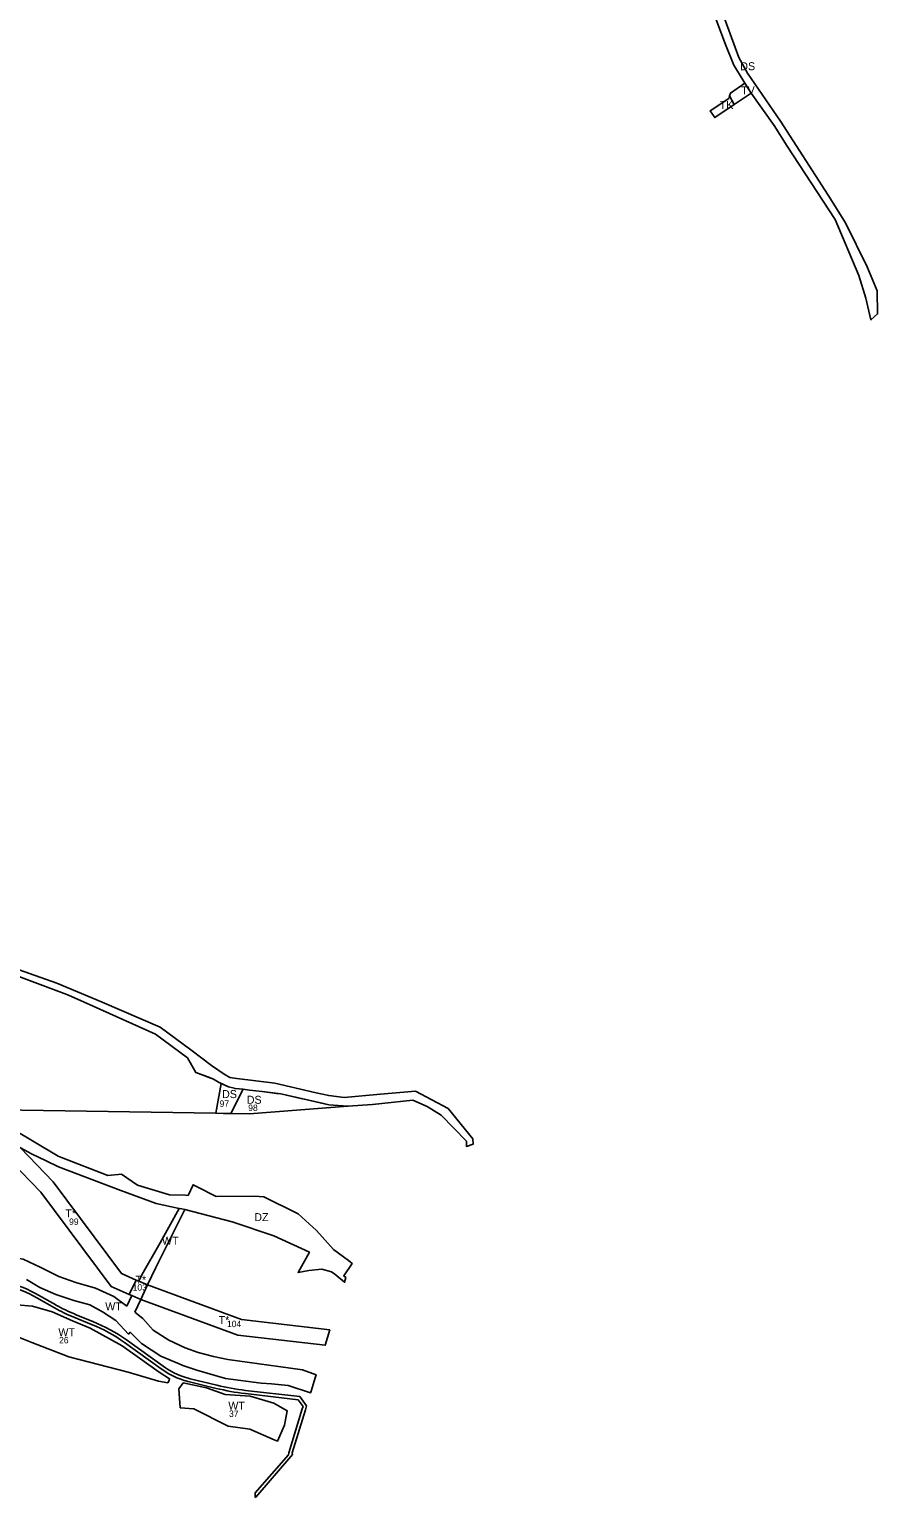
# Model space of a CAD drawing. Extents: x -521621 to -516769, y -1190068 to -1185078.
# Drawn here: x -517829 to -516769, y -1188185 to -1186349 of the extents above; entities that cross this region are included whole.
import ezdxf

# ---------------------------------------------------------------- set-up
doc = ezdxf.new("R2010")
doc.units = 0
for name, color, linetype in [('fpl_id', 7, 'Continuous'), ('v_infrastr_n', 7, 'Continuous'), ('v_infrastr_s', 7, 'Continuous'), ('voda_n', 7, 'Continuous'), ('voda_s', 7, 'Continuous')]:
    doc.layers.add(name, color=color, linetype=linetype)

msp = doc.modelspace()

# ---------------------------------------------------------------- linework, layer by layer
at = {"layer": 'v_infrastr_n'}
for points in [[(-518125.5, -1187497.4), (-518115.5, -1187495.9), (-517932.8, -1187498.8), (-517912.3, -1187500.7), (-517903.3, -1187502.1), (-517892, -1187510.1), (-517869.1, -1187523.4), (-517829, -1187538.4), (-517785.5, -1187554.6), (-517780, -1187556.7), (-517749.3, -1187570.2), (-517671.4, -1187605.2), (-517631.2, -1187635), (-517621, -1187653.2), (-517598.9, -1187661.5), (-517592.8, -1187665.3), (-517589.2, -1187666.9), (-517596.1, -1187704.1), (-517892.4, -1187699.4)], [(-517840.1, -1187747.4), (-517799.3, -1187789.7), (-517714, -1187904.5), (-517695.5, -1187912.6), (-517704.3, -1187930.6), (-517726.9, -1187920.7), (-517814.6, -1187802.6), (-517851.6, -1187764.3), (-517939.7, -1187711.3)]]:
    msp.add_lwpolyline(points, dxfattribs=at)
for points in [[(-517589.2, -1187666.9), (-517580.3, -1187671.2), (-517573, -1187672.9), (-517572.6, -1187673), (-517572, -1187673.1), (-517562, -1187674.2), (-517577.2, -1187704.4), (-517586.4, -1187704.3), (-517596.1, -1187704.1)], [(-517553.7, -1187675.1), (-517537.9, -1187676.9), (-517514.8, -1187680), (-517489.9, -1187685.6), (-517487.3, -1187686.2), (-517454.8, -1187693.5), (-517430.9, -1187695.3), (-517553.8, -1187704.8), (-517577.2, -1187704.4), (-517562, -1187674.2)], [(-517681.4, -1187918.8), (-517689.8, -1187936.9), (-517701, -1187932), (-517704.3, -1187930.6), (-517695.5, -1187912.6), (-517692.2, -1187914)], [(-517681.4, -1187918.8), (-517563.8, -1187961.9), (-517453.5, -1187975), (-517459.3, -1187994.2), (-517568.5, -1187981.4), (-517689.8, -1187936.9)]]:
    msp.add_lwpolyline(points, close=True, dxfattribs=at)
at = {"layer": 'v_infrastr_s'}
for points in [[(-516974.7, -1186295.2), (-516942.5, -1186384.5), (-516931.3, -1186403.9), (-516890.3, -1186464.1), (-516830.8, -1186556.5), (-516809, -1186591.3), (-516781.7, -1186646.1), (-516769.3, -1186676.3), (-516768.8, -1186705), (-516777.3, -1186712.5), (-516783.5, -1186685.2), (-516792.5, -1186656.8), (-516821.9, -1186586.9), (-516882, -1186495.3), (-516898.3, -1186469.5), (-516927, -1186429.2), (-516934.8, -1186416.4), (-516937.1, -1186412.6), (-516948.4, -1186394), (-516959.1, -1186368.4), (-516979.8, -1186312.4)], [(-517863.1, -1187517.3), (-517794.6, -1187541.5), (-517738.2, -1187565.4), (-517665.4, -1187596.6), (-517627.3, -1187624.7), (-517601.2, -1187644.4), (-517585.7, -1187655.1), (-517578.6, -1187659.3), (-517569.9, -1187660.8), (-517522.1, -1187666.6), (-517470.4, -1187678.7), (-517454.9, -1187682.1), (-517435.4, -1187684.4), (-517390.3, -1187680.3), (-517346.6, -1187676.5), (-517305.6, -1187698.2), (-517274.9, -1187736.2), (-517274.3, -1187742.7), (-517282.7, -1187745.6), (-517282.7, -1187739.2), (-517314.4, -1187706.7), (-517331.9, -1187695.8), (-517349.6, -1187687.8), (-517388.3, -1187692), (-517400.3, -1187693.2), (-517430.9, -1187695.3)], [(-517785.5, -1187554.6), (-517829, -1187538.4)], [(-517780, -1187556.7), (-517785.5, -1187554.6)], [(-517749.3, -1187570.2), (-517780, -1187556.7)], [(-517671.4, -1187605.2), (-517749.3, -1187570.2)], [(-517631.2, -1187635), (-517671.4, -1187605.2)], [(-517621, -1187653.2), (-517631.2, -1187635)], [(-517606, -1187658.8), (-517621, -1187653.2)], [(-517598.9, -1187661.5), (-517606, -1187658.8)], [(-517592.8, -1187665.3), (-517598.9, -1187661.5)], [(-517580.3, -1187671.2), (-517592.8, -1187665.3)], [(-517573, -1187672.9), (-517580.3, -1187671.2)], [(-517572.6, -1187673), (-517573, -1187672.9)], [(-517572, -1187673.1), (-517572.6, -1187673)], [(-517562, -1187674.2), (-517572, -1187673.1)], [(-517553.7, -1187675.1), (-517562, -1187674.2)], [(-517537.9, -1187676.9), (-517553.7, -1187675.1)], [(-517520.3, -1187679.3), (-517537.9, -1187676.9)], [(-517514.8, -1187680), (-517520.3, -1187679.3)], [(-517520.3, -1187679.3), (-517520.3, -1187679.3)], [(-517461.3, -1187692.1), (-517514.8, -1187680)], [(-517454.8, -1187693.5), (-517461.3, -1187692.1)], [(-517430.9, -1187695.3), (-517454.8, -1187693.5)], [(-517788.7, -1187759.5), (-517793.2, -1187757.7), (-517879.3, -1187706.6), (-517892.4, -1187699.4), (-517923.8, -1187698.9)], [(-517923.8, -1187698.9), (-517890.9, -1187719.9), (-517826.4, -1187754.9), (-517808.2, -1187763.5)], [(-517808.2, -1187763.5), (-517792.5, -1187771)], [(-517792.5, -1187771), (-517714.8, -1187800.5)], [(-517730.9, -1187782), (-517788.7, -1187759.5)], [(-517713.7, -1187780.1), (-517730.9, -1187782)], [(-517693.7, -1187794), (-517713.7, -1187780.1)], [(-517714.8, -1187800.5), (-517670.7, -1187817)], [(-517653.7, -1187806.2), (-517693.7, -1187794)], [(-517633.7, -1187806.7), (-517653.7, -1187806.2)], [(-517638.3, -1187823.7), (-517634.7, -1187824.6), (-517575.5, -1187839.9), (-517523.4, -1187857.3), (-517479.1, -1187877.8), (-517493.1, -1187903.4), (-517479.6, -1187900.6), (-517463.3, -1187899), (-517451.4, -1187902.5), (-517447.2, -1187905.4), (-517435.1, -1187915.3), (-517433.4, -1187909.6), (-517436, -1187907.5), (-517425.5, -1187892.1), (-517430.2, -1187888.3), (-517449.1, -1187874.4), (-517470.2, -1187850.9), (-517492.9, -1187829.8), (-517535.8, -1187808.7), (-517547.5, -1187807.7), (-517595.7, -1187808.3), (-517620.2, -1187795.8), (-517624.5, -1187793.5), (-517630.7, -1187806.8)], [(-517630.7, -1187806.8), (-517633.7, -1187806.7)], [(-517670.7, -1187817), (-517641.6, -1187823)], [(-517641.6, -1187823), (-517638.3, -1187823.7)], [(-517819.5, -1187934.9), (-517797.8, -1187947.3)], [(-517795.8, -1187943.8), (-517817.6, -1187931.4)], [(-517749.7, -1187964.4), (-517771.9, -1187955.5)], [(-517773.4, -1187959.2), (-517751.2, -1187968.1)], [(-517710.1, -1187990.7), (-517664.1, -1188023.7)], [(-517661.8, -1188020.4), (-517707.8, -1187987.5)], [(-517628.9, -1188039.9), (-517595.5, -1188048)], [(-517594.6, -1188044.1), (-517627.9, -1188036)], [(-517559.1, -1188054.5), (-517559.1, -1188054.5), (-517493.2, -1188062.2), (-517487, -1188070.6)], [(-517484.1, -1188074.7), (-517482.6, -1188069.9), (-517491, -1188058.4), (-517558.7, -1188050.6), (-517558.7, -1188050.6)], [(-517487, -1188070.6), (-517487.9, -1188073.5), (-517504.8, -1188128.7), (-517505, -1188131.2)], [(-517502.3, -1188133.3), (-517500.2, -1188130.8), (-517500.7, -1188128.8), (-517484.1, -1188074.7)], [(-517505, -1188131.2), (-517546.8, -1188178.7), (-517546.8, -1188181.4), (-517546.7, -1188184.6)], [(-517546.7, -1188184.6), (-517546, -1188183.9), (-517502.3, -1188133.3)]]:
    msp.add_lwpolyline(points, dxfattribs=at)
for points in [[(-516954, -1186432.6), (-516952.7, -1186428.9), (-516934.8, -1186416.4), (-516927, -1186429.2), (-516940.6, -1186438.3), (-516948.1, -1186443.3)], [(-516948.1, -1186443.3), (-516972.3, -1186459.5), (-516978, -1186451.1), (-516955, -1186435.7), (-516954, -1186432.6)]]:
    msp.add_lwpolyline(points, close=True, dxfattribs=at)
for centre, radius, start, end in [((-517892.9, -1188063.4), 152, 60.2686, 92.4562), ((-517892.9, -1188063.4), 148, 60.2686, 92.4562), ((-517697.6, -1187771.9), 202, 240.2676, 247.9824), ((-517697.6, -1187771.9), 198, 240.2676, 247.9824), ((-517825.4, -1188151.7), 198, 54.3846, 67.9824), ((-517825.4, -1188151.7), 202, 54.3846, 67.9824), ((-517604.7, -1187940.8), 102, 234.3839, 251.1715), ((-517604.7, -1187940.8), 98, 234.3839, 249.7913), ((-517604.7, -1187940.8), 98, 249.7913, 256.3001), ((-517604.7, -1187940.8), 102, 251.1715, 256.3001), ((-517524, -1187754.6), 298, 256.2985, 263.3154), ((-517524, -1187754.6), 302, 256.2985, 263.316)]:
    msp.add_arc(centre, radius, start, end, dxfattribs=at)
at = {"layer": 'voda_n'}
for points in [[(-517864.3, -1187942), (-517825.2, -1187945.2), (-517800.5, -1187952.5), (-517775.2, -1187963.8), (-517753.1, -1187972.8), (-517713, -1187994.8), (-517667, -1188027.7), (-517653.8, -1188036), (-517654.4, -1188038.4), (-517656, -1188041), (-517667.8, -1188038.9), (-517705.4, -1188027.8), (-517779.6, -1188008.6), (-517826.1, -1187990.9), (-517888.9, -1187965.6), (-517914, -1187954.7), (-517902.2, -1187948.9), (-517887.2, -1187944.5)], [(-517584.2, -1188055.5), (-517553, -1188057.6), (-517523.4, -1188066.4), (-517506.7, -1188076.1), (-517510.1, -1188093.9), (-517519.1, -1188114.2), (-517523.1, -1188112.4), (-517553.3, -1188098.9), (-517580.7, -1188095.1), (-517623.5, -1188073.6), (-517640.4, -1188072.3), (-517642.2, -1188048.5), (-517636.8, -1188041.3), (-517607.7, -1188047.3)]]:
    msp.add_lwpolyline(points, close=True, dxfattribs=at)
at = {"layer": 'voda_s'}
for points in [[(-517681.4, -1187918.8), (-517671.1, -1187896.8), (-517634.7, -1187824.6), (-517638.3, -1187823.7), (-517641.6, -1187823), (-517665.7, -1187866.1), (-517688.4, -1187906.2), (-517692.2, -1187914)], [(-517707.4, -1187945.2), (-517723.6, -1187933.3), (-517746.3, -1187922.6), (-517771, -1187915.8), (-517792.3, -1187908.1), (-517815.6, -1187896.7), (-517836.9, -1187886.7), (-517855, -1187883.6), (-517879.5, -1187882.2), (-517899.4, -1187882.5), (-517917.8, -1187883), (-517936, -1187884), (-517954.2, -1187886.1), (-517976, -1187885.9), (-517976, -1187880.1), (-517982.9, -1187878.1), (-517987, -1187884.5), (-518002.4, -1187881.3), (-518021.9, -1187875.1), (-518058.6, -1187863.4), (-518097.1, -1187853.8), (-518114.6, -1187845), (-518128.2, -1187835.9), (-518129.6, -1187834.7)], [(-517832.6, -1187912), (-517815.8, -1187921.9), (-517796, -1187930.5), (-517773.5, -1187938.1), (-517753.4, -1187943.6), (-517737.8, -1187952.4), (-517720.9, -1187963.2), (-517705, -1187980.2), (-517703.1, -1187977.9), (-517688.9, -1187991.9), (-517664.8, -1188007.8), (-517641.7, -1188017.5), (-517637.1, -1188019.4), (-517619.8, -1188025.2), (-517584.1, -1188035.7), (-517539.4, -1188041.4), (-517526.3, -1188042.2), (-517505.7, -1188044.4), (-517477.6, -1188053.5), (-517477, -1188051.4), (-517471.9, -1188034.9), (-517471.1, -1188032.5), (-517470.7, -1188031.1), (-517487.7, -1188024.8), (-517517.6, -1188020.9), (-517542, -1188017.5), (-517580.9, -1188012), (-517598.9, -1188008.1), (-517617.9, -1188003.2), (-517634.3, -1187997.2), (-517654.8, -1187987.8), (-517674.1, -1187975.4), (-517687.1, -1187960.6), (-517697.3, -1187952.8)], [(-517692.2, -1187914), (-517681.4, -1187918.8)], [(-517701, -1187932), (-517707.4, -1187945.2)], [(-517689.8, -1187936.9), (-517701, -1187932)], [(-517697.3, -1187952.8), (-517689.8, -1187936.9)]]:
    msp.add_lwpolyline(points, dxfattribs=at)

# ---------------------------------------------------------------- texts
at = {"layer": 'fpl_id'}
for s, p in [('97', (-517591.3, -1187696.1)), ('98', (-517555.5, -1187701.3)), ('99', (-517779.4, -1187843.7)), ('103', (-517700, -1187925.8)), ('104', (-517582.1, -1187971.5)), ('26', (-517791.9, -1187991.8)), ('37', (-517579.5, -1188083.7))]:
    msp.add_text(s, height=8, dxfattribs=at).set_placement(p)
at = {"layer": 'v_infrastr_n'}
for s, p in [('DS', (-517588.2, -1187685.2)), ('DS', (-517557.3, -1187692.3)), ('T*', (-517784, -1187834.3)), ('T*', (-517696.5, -1187917.3)), ('T*', (-517592.5, -1187967.7))]:
    msp.add_text(s, height=10, dxfattribs=at).set_placement(p)
at = {"layer": 'v_infrastr_s'}
for s, p in [('DS', (-516940.5, -1186400.4)), ('TV', (-516939.5, -1186430.6)), ('TK', (-516966.2, -1186448.7)), ('DZ', (-517547.9, -1187839))]:
    msp.add_text(s, height=10, dxfattribs=at).set_placement(p)
at = {"layer": 'voda_n'}
for p in [(-517792.8, -1187982.8), (-517580.4, -1188074.6)]:
    msp.add_text('WT', height=10, dxfattribs=at).set_placement(p)
at = {"layer": 'voda_s'}
for p in [(-517663.3, -1187868.5), (-517734.2, -1187950.5)]:
    msp.add_text('WT', height=10, dxfattribs=at).set_placement(p)

doc.saveas('drawing.dxf')
